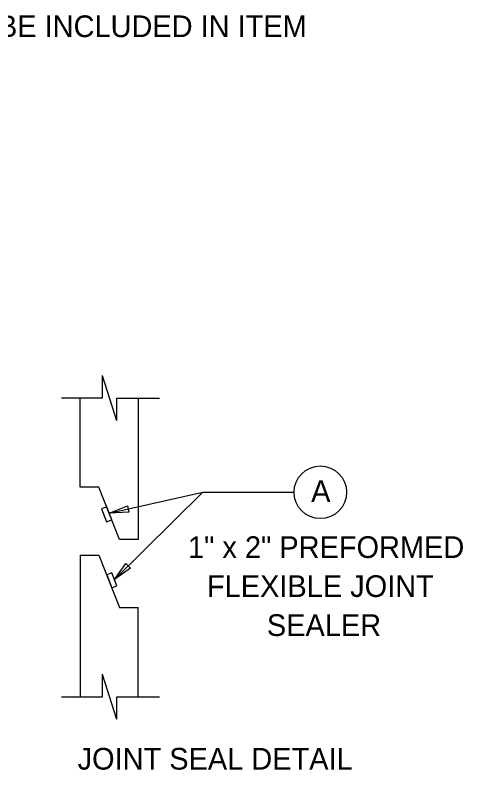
# Model space of a CAD drawing. Extents: x -1609 to 1184, y -412 to 394.
# Drawn here: x -928.72 to -922.93, y -269.89 to -260.13 of the extents above; entities that cross this region are included whole.
import ezdxf

# ---------------------------------------------------------------- set-up
doc = ezdxf.new("R2010")
doc.units = 0
for name, color, linetype in [('Default', 7, 'Continuous'), ('SH_Data', 7, 'Continuous'), ('ST_Details', 7, 'Continuous'), ('ST_Text', 7, 'Continuous')]:
    doc.layers.add(name, color=color, linetype=linetype)

msp = doc.modelspace()

# ---------------------------------------------------------------- linework, layer by layer
at = {"layer": 'Default'}
for points in [[(-927.2694, -266.4748), (-927.2509, -266.5561), (-927.5038, -266.5708)], [(-927.2884, -267.2194), (-927.2298, -267.2787), (-927.4369, -267.4247)]]:
    msp.add_lwpolyline(points, close=True, dxfattribs=at)
at = {"layer": 'ST_Details'}
for p, q in [((-927.5958, -264.7906), (-927.4119, -265.371)), ((-927.5958, -264.7906), (-927.5958, -265.0844)), ((-927.5958, -265.0844), (-928.1206, -265.0844)), ((-927.8788, -266.2325), (-927.8788, -265.0844)), ((-926.8548, -265.088), (-927.4119, -265.088)), ((-927.4119, -265.088), (-927.4119, -265.371)), ((-927.1288, -265.088), (-927.1288, -266.9091)), ((-927.6366, -266.2325), (-927.8788, -266.2325)), ((-927.8788, -266.2325), (-927.8788, -266.2325)), ((-927.371, -266.9091), (-927.6366, -266.2325)), ((-927.1288, -266.9091), (-927.371, -266.9091)), ((-927.8788, -267.112), (-927.8788, -268.9446)), ((-927.8788, -267.1127), (-927.6366, -267.1127)), ((-927.6366, -267.1127), (-927.371, -267.7893)), ((-927.371, -267.7893), (-927.1288, -267.7893)), ((-927.1288, -268.9482), (-927.1288, -267.7893)), ((-927.5958, -268.6508), (-927.4119, -269.2312)), ((-927.5958, -268.6508), (-927.5958, -268.9446)), ((-927.5958, -268.9446), (-928.1206, -268.9446)), ((-926.8548, -268.9482), (-927.4119, -268.9482)), ((-927.4119, -268.9482), (-927.4119, -269.2312))]:
    msp.add_line(p, q, dxfattribs=at)
for points in [[(-927.604, -266.5125), (-927.5376, -266.6817), (-927.4706, -266.6554), (-927.537, -266.4862)], [(-927.537, -267.3664), (-927.4706, -267.5356), (-927.4037, -267.5093), (-927.4701, -267.3401)]]:
    msp.add_lwpolyline(points, close=True, dxfattribs=at)
at = {"layer": 'ST_Text'}
for p, q in [((-927.5038, -266.5708), (-926.2951, -266.2964)), ((-927.4369, -267.4247), (-926.2951, -266.2964)), ((-926.2951, -266.2964), (-925.1137, -266.2964))]:
    msp.add_line(p, q, dxfattribs=at)
msp.add_circle((-924.7738, -266.2994), 0.34, dxfattribs=at)

# ---------------------------------------------------------------- texts
at = {"layer": 'SH_Data'}
for s, p in [('THE PLACEMENT OF THE LOW STRENGTH MOTAR SHALL BE INCLUDED IN ITEM', (-939.5322, -260.4189)), ('A', (-924.8925, -266.4235)), ('1" x 2" PREFORMED', (-926.4855, -267.1477)), ('FLEXIBLE JOINT', (-926.2399, -267.6517)), ('SEALER', (-925.4652, -268.1557)), ('JOINT SEAL DETAIL', (-927.9134, -269.8819))]:
    msp.add_text(s, height=0.28, dxfattribs=at).set_placement(p)

doc.saveas('drawing.dxf')
